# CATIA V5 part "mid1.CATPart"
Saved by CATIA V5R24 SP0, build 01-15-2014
Part number: Part3
Bounding box of the stored display mesh (mm): x -59.983 to 59.983, y -59.992 to 59.992, z 0 to 79.995
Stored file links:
  G:\내 드라이브\04_WORK\00_LECTURE\CAD2020\exam\mid1.CATPart
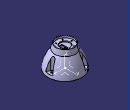
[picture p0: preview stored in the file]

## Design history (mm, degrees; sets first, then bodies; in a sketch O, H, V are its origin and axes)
AxisSystem1: origin (0, 0, 0), X (1, 0, 0), Y (0, 1, 0), Z (0, 0, 1)
Set1
  Sketch1 on YZ plane of AxisSystem1, origin (0, 0, 0), H (0, 1, 0), V (0, 0, 1)
    arc A1 centre (-59.3023, -12.9209) radius 120 from (60, 0) to (36, 60) ccw
    point P2 (60, 0)
    point P3 (36, 60)
    line L1 (36, 60) -> (32.1124, 80)
    point P4 (32.1124, 80)
    axis line L2 (0, -9.5014) -> (0, 86.5836)
    point P5 (0, -9.5014)
    line L3 (60, 0) -> (0, 0)
    point P7 (0, 80)
    line L4 (0, 80) -> (32.1124, 80)
    radius A1 = 120
    distance P2 V = 60
    distance P3 V = 36
    distance P3 H = 60
    angle L1 V = 11
    distance P4 H = 80
    coincidence: P2 H, P5 V, P7 L2
    vertical: L2 V
    horizontal: L3 H, L4 H
Body1 (main body)
  Shaft1: profile Sketch1, axis Sketch1.L2, angle 360
  Sketch2 on face of Shaft1 from Sketch1.L4, origin (0.2479, 13.4878, 80), H (1, 0, 0), V (0, 1, 0)
    point P1 (-0.2479, -13.4878)
    reference projected circle E1 centre (-0.2479, -13.4878) radius 32.1124 from edge [face of Shaft1 from Sketch1.L1 | face of Shaft1 from Sketch1.L4]
    concentricity: E1 P1
  Hole1: placed by Sketch2, at (0, 0, 80) direction (0, 0, -1), diameter 60, depth 8
  Sketch3 on face of Hole1, origin (-13.9837, 4.9567, 72), H (1, 0, 0), V (0, 1, 0)
    point P1 (13.9837, -4.9567)
    reference projected circle E1 centre (13.9837, -4.9567) radius 30 from edge [face of Hole1 | face of Hole1]
    concentricity: E1 P1
  Hole2: placed by Sketch3, at (0, 0, 72) direction (0, 0, -1), diameter 35, depth 4
  TritangentFillet1: Face1 face of Shaft1 from Sketch1.L1, Face2 face of Hole1, RemoveFace face of Shaft1 from Sketch1.L4
  Sketch4 on XY plane of AxisSystem1, origin (0, 0, 0), H (1, 0, 0), V (0, 1, 0)
    line L1 (67.9399, 17.1256) -> (44.4385, 7.391)
    arc A1 centre (47.5, 0) radius 8 from (44.4385, 7.391) to (44.4385, -7.391) ccw
    point P3 (47.5, 0)
    line L2 (44.4385, -7.391) -> (67.9399, -17.1256)
    angle L1 L2 = 45
    radius A1 = 8
    distance P3 V = 47.5
    tangency: A1 L1, L2 A1
    symmetry: L2 L1 H
  Pocket1: profile Sketch4, direction (0, 0, 1), through (limit type 3), opposite side length -10
  CircPattern1: of Pocket1, instances 3, angular step 120, axis from face of Shaft1 from Sketch1.L1
  Shell1: ExtOffset 0, Face face of Shaft1 from Sketch1.L3, IntOffset 3
  Sketch5 on start face of Pocket1, origin (45.027, 1.9793, 10), H (1, 0, 0), V (0, 1, 0)
    point P1 (2.473, -1.9793)
    reference projected arc E1 centre (2.473, -1.9793) radius 8 from (-0.5885, 5.4117) to (-0.5885, -9.3703) ccw from edge [start face of Pocket1 | face of Pocket1 from Sketch4.A1]
    concentricity: E1 P1
  Hole3: placed by Sketch5, at (47.5, 0, 10) direction (0, 0, -1), diameter 7, through (limit type 3)
  CircPattern2: of Hole3, instances 3, angular step 120, axis from face of Shaft1 from Sketch1.L1
  Sketch6 on face of Hole1, origin (0, 0, 72), H (1, 0, 0), V (0, 1, 0)
    point P1 (23.75, 0)
    distance P1 V = 23.75
    coincidence: P1 H
  Hole4: placed by Sketch6, at (23.75, 0, 72) direction (0, 0, -1), diameter 4, through (limit type 3)
  CircPattern3: of Hole4, instances 6, angular step 60, axis from face of Hole1
  Sketch7 on XY plane of AxisSystem1, origin (0, 0, 0), H (1, 0, 0), V (0, 1, 0)
    point P1 (6, 0)
    line L1 (12, 11) -> (12, -11)
    line L2 (12, -11) -> (0, -11)
    line L3 (0, -11) -> (0, 11)
    line L4 (0, 11) -> (12, 11)
    distance L4 L2 = 22
    distance L1 L3 = 12
    coincidence: P1 H, L3 V
    vertical: L1 V, L3 V
    horizontal: L2 H, L4 H
    equidistance: L1 L3 P1, L2 L4 P1
  Pocket2: profile Sketch7, direction (0, 0, 1), through (limit type 3)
